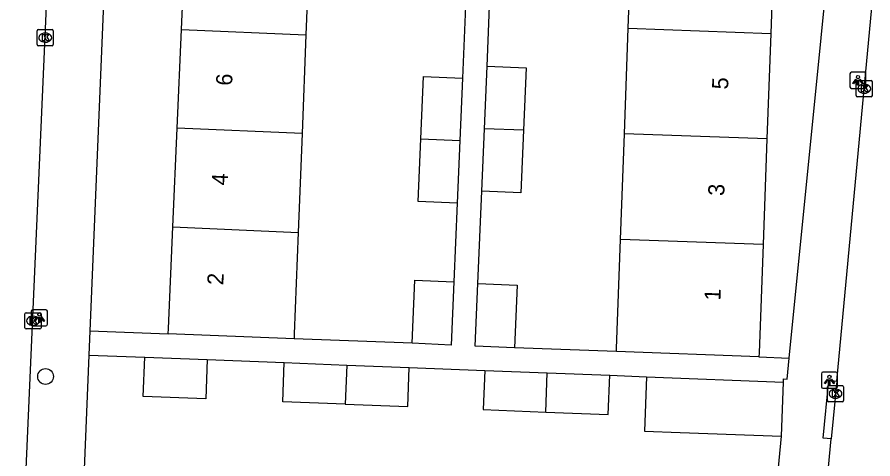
# Model space of a CAD drawing. Extents: x 161355 to 162026, y 386504 to 387459.
# Drawn here: x 161733.6 to 161786.7, y 386670 to 386697.4 of the extents above; entities that cross this region are included whole.
import ezdxf

# ---------------------------------------------------------------- set-up
doc = ezdxf.new("R2010")
doc.units = 0
for name, color, linetype in [('IMGEO_Boom', 7, 'Continuous'), ('IMGEO_Kolk', 7, 'Continuous'), ('IMGEO_Lichtpunt', 7, 'Continuous'), ('IMGEO_Muur', 7, 'Continuous'), ('IMGEO_Pand', 7, 'Continuous'), ('IMGEO_Pand_nummerreeks', 7, 'Continuous'), ('IMGEO_Rijbaan_lokaal_open', 7, 'Continuous'), ('IMGEO_Voetpad_open', 7, 'Continuous')]:
    doc.layers.add(name, color=color, linetype=linetype)

msp = doc.modelspace()

# ---------------------------------------------------------------- linework, layer by layer
at = {"layer": 'IMGEO_Boom'}
msp.add_circle((161735.346, 386675.123), 0.489, dxfattribs=at)
at = {"layer": 'IMGEO_Kolk'}
for p, q in [((161734.826, 386695.717), (161734.826, 386696.569)), ((161734.901, 386696.643), (161735.753, 386696.643)), ((161735.314, 386696.423), (161735.339, 386696.423)), ((161735.827, 386696.569), (161735.827, 386695.717)), ((161735.337, 386695.863), (161735.312, 386695.863)), ((161735.753, 386695.643), (161734.901, 386695.643)), ((161785.645, 386692.551), (161785.645, 386693.403)), ((161785.72, 386693.477), (161786.572, 386693.477)), ((161786.133, 386693.257), (161786.158, 386693.257)), ((161786.646, 386693.403), (161786.646, 386692.551)), ((161786.156, 386692.697), (161786.131, 386692.697)), ((161786.572, 386692.477), (161785.72, 386692.477)), ((161734.065, 386678.151), (161734.065, 386679.003)), ((161734.14, 386679.077), (161734.992, 386679.077)), ((161734.553, 386678.857), (161734.578, 386678.857)), ((161735.066, 386679.003), (161735.066, 386678.151)), ((161734.576, 386678.297), (161734.551, 386678.297)), ((161734.992, 386678.077), (161734.14, 386678.077)), ((161783.86, 386673.63), (161783.86, 386674.482)), ((161783.935, 386674.556), (161784.787, 386674.556)), ((161784.861, 386674.482), (161784.861, 386673.63)), ((161784.348, 386674.336), (161784.373, 386674.336)), ((161784.787, 386673.556), (161783.935, 386673.556)), ((161784.371, 386673.776), (161784.346, 386673.776))]:
    msp.add_line(p, q, dxfattribs=at)
for points in [[(161734.826, 386695.717), (161734.826, 386696.569)], [(161734.901, 386696.643), (161735.753, 386696.643)], [(161735.147, 386696.343), (161735.27, 386696.343), (161735.27, 386696.192), (161735.4, 386696.343), (161735.564, 386696.343), (161735.418, 386696.192), (161735.571, 386695.943), (161735.419, 386695.943), (161735.334, 386696.107), (161735.27, 386696.04), (161735.27, 386695.943), (161735.147, 386695.943), (161735.147, 386696.343)], [(161735.827, 386696.569), (161735.827, 386695.717)], [(161735.753, 386695.643), (161734.901, 386695.643)], [(161785.645, 386692.551), (161785.645, 386693.403)], [(161785.72, 386693.477), (161786.572, 386693.477)], [(161785.966, 386693.177), (161786.089, 386693.177), (161786.089, 386693.026), (161786.219, 386693.177), (161786.383, 386693.177), (161786.237, 386693.026), (161786.39, 386692.777), (161786.238, 386692.777), (161786.153, 386692.941), (161786.089, 386692.874), (161786.089, 386692.777), (161785.966, 386692.777), (161785.966, 386693.177)], [(161786.646, 386693.403), (161786.646, 386692.551)], [(161786.572, 386692.477), (161785.72, 386692.477)], [(161734.065, 386678.151), (161734.065, 386679.003)], [(161734.14, 386679.077), (161734.992, 386679.077)], [(161734.386, 386678.777), (161734.509, 386678.777), (161734.509, 386678.626), (161734.639, 386678.777), (161734.803, 386678.777), (161734.657, 386678.626), (161734.81, 386678.377), (161734.658, 386678.377), (161734.573, 386678.541), (161734.509, 386678.474), (161734.509, 386678.377), (161734.386, 386678.377), (161734.386, 386678.777)], [(161735.066, 386679.003), (161735.066, 386678.151)], [(161734.992, 386678.077), (161734.14, 386678.077)], [(161783.86, 386673.63), (161783.86, 386674.482)], [(161783.935, 386674.556), (161784.787, 386674.556)], [(161784.861, 386674.482), (161784.861, 386673.63)], [(161784.181, 386674.256), (161784.304, 386674.256), (161784.304, 386674.105), (161784.434, 386674.256), (161784.598, 386674.256), (161784.452, 386674.105), (161784.605, 386673.856), (161784.453, 386673.856), (161784.368, 386674.02), (161784.304, 386673.953), (161784.304, 386673.856), (161784.181, 386673.856), (161784.181, 386674.256)], [(161784.787, 386673.556), (161783.935, 386673.556)]]:
    msp.add_lwpolyline(points, dxfattribs=at)
for centre, start, end in [((161734.903, 386696.567), 91.552, 178.448), ((161734.903, 386696.567), 91.552, 178.448), ((161735.751, 386696.567), 1.552, 88.448), ((161735.751, 386696.567), 1.552, 88.448), ((161734.903, 386695.719), 181.552, 268.448), ((161734.903, 386695.719), 181.552, 268.448), ((161735.751, 386695.719), 271.552, 358.448), ((161735.751, 386695.719), 271.552, 358.448), ((161785.722, 386693.401), 91.552, 178.448), ((161785.722, 386693.401), 91.552, 178.448), ((161786.57, 386693.401), 1.552, 88.448), ((161786.57, 386693.401), 1.552, 88.448), ((161785.722, 386692.553), 181.552, 268.448), ((161785.722, 386692.553), 181.552, 268.448), ((161786.57, 386692.553), 271.552, 358.448), ((161786.57, 386692.553), 271.552, 358.448), ((161734.142, 386679.001), 91.552, 178.448), ((161734.142, 386679.001), 91.552, 178.448), ((161734.99, 386679.001), 1.552, 88.448), ((161734.99, 386679.001), 1.552, 88.448), ((161734.142, 386678.153), 181.552, 268.448), ((161734.142, 386678.153), 181.552, 268.448), ((161734.99, 386678.153), 271.552, 358.448), ((161734.99, 386678.153), 271.552, 358.448), ((161783.937, 386674.48), 91.552, 178.448), ((161783.937, 386674.48), 91.552, 178.448), ((161784.785, 386674.48), 1.552, 88.448), ((161784.785, 386674.48), 1.552, 88.448), ((161783.937, 386673.632), 181.552, 268.448), ((161783.937, 386673.632), 181.552, 268.448), ((161784.785, 386673.632), 271.552, 358.448), ((161784.785, 386673.632), 271.552, 358.448)]:
    msp.add_arc(centre, 0.0765, start, end, dxfattribs=at)
for centre, major_axis, ratio, start_param, end_param in [((161735.313, 386696.143), (-0.387, 0.002), 0.722429, 4.712389, 7.853982), ((161735.338, 386696.143), (-0.39, 0.002), 0.717154, 1.570796, 4.712389), ((161786.132, 386692.977), (-0.387, 0.002), 0.722429, 4.712389, 7.853982), ((161786.157, 386692.977), (-0.39, 0.002), 0.717154, 1.570796, 4.712389), ((161734.552, 386678.577), (-0.387, 0.002), 0.722429, 4.712389, 7.853982), ((161734.577, 386678.577), (-0.39, 0.002), 0.717154, 1.570796, 4.712389), ((161784.347, 386674.056), (-0.387, 0.002), 0.722429, 4.712389, 7.853982), ((161784.372, 386674.056), (-0.39, 0.002), 0.717154, 1.570796, 4.712389)]:
    msp.add_ellipse(centre, major_axis=major_axis, ratio=ratio, start_param=start_param, end_param=end_param, dxfattribs=at)
at = {"layer": 'IMGEO_Lichtpunt'}
for p, q in [((161785.256, 386693.899), (161785.256, 386693.092)), ((161785.256, 386693.899), (161785.256, 386693.092)), ((161786.158, 386693.994), (161785.35, 386693.994)), ((161786.158, 386693.994), (161785.35, 386693.994)), ((161786.252, 386693.092), (161786.252, 386693.899)), ((161786.252, 386693.092), (161786.252, 386693.899)), ((161785.35, 386692.998), (161786.158, 386692.998)), ((161785.35, 386692.998), (161786.158, 386692.998)), ((161735.364, 386679.266), (161734.556, 386679.266)), ((161735.364, 386679.266), (161734.556, 386679.266)), ((161734.462, 386679.171), (161734.462, 386678.364)), ((161734.462, 386679.171), (161734.462, 386678.364)), ((161735.458, 386678.364), (161735.458, 386679.171)), ((161735.458, 386678.364), (161735.458, 386679.171)), ((161734.556, 386678.27), (161735.364, 386678.27)), ((161734.556, 386678.27), (161735.364, 386678.27)), ((161783.484, 386675.299), (161783.484, 386674.492)), ((161783.484, 386675.299), (161783.484, 386674.492)), ((161784.386, 386675.394), (161783.578, 386675.394)), ((161784.386, 386675.394), (161783.578, 386675.394)), ((161784.48, 386674.492), (161784.48, 386675.299)), ((161784.48, 386674.492), (161784.48, 386675.299)), ((161783.578, 386674.398), (161784.386, 386674.398)), ((161783.578, 386674.398), (161784.386, 386674.398))]:
    msp.add_line(p, q, dxfattribs=at)
for points in [[(161785.63, 386693.563), (161785.669, 386693.535), (161785.481, 386693.273), (161785.443, 386693.3), (161785.63, 386693.563)], [(161785.732, 386693.515), (161785.779, 386693.515), (161785.779, 386693.193), (161785.732, 386693.193), (161785.732, 386693.515)], [(161785.842, 386693.535), (161785.88, 386693.562), (161786.067, 386693.3), (161786.028, 386693.272), (161785.842, 386693.535)], [(161734.836, 386678.835), (161734.875, 386678.807), (161734.687, 386678.545), (161734.649, 386678.572), (161734.836, 386678.835)], [(161734.938, 386678.787), (161734.985, 386678.787), (161734.985, 386678.465), (161734.938, 386678.465), (161734.938, 386678.787)], [(161735.048, 386678.807), (161735.086, 386678.834), (161735.273, 386678.572), (161735.234, 386678.544), (161735.048, 386678.807)], [(161783.858, 386674.963), (161783.897, 386674.935), (161783.709, 386674.673), (161783.671, 386674.7), (161783.858, 386674.963)], [(161783.96, 386674.915), (161784.007, 386674.915), (161784.007, 386674.593), (161783.96, 386674.593), (161783.96, 386674.915)], [(161784.07, 386674.935), (161784.108, 386674.962), (161784.295, 386674.7), (161784.256, 386674.672), (161784.07, 386674.935)]]:
    msp.add_lwpolyline(points, dxfattribs=at)
for centre in [(161785.755, 386693.697), (161734.961, 386678.969), (161783.983, 386675.097)]:
    msp.add_circle(centre, 0.0994, dxfattribs=at)
for centre, start, end in [((161785.35, 386693.899), 90, 180), ((161785.35, 386693.899), 90, 180), ((161786.158, 386693.899), 0, 90), ((161786.158, 386693.899), 0, 90), ((161785.35, 386693.092), 180, 270), ((161785.35, 386693.092), 180, 270), ((161786.158, 386693.092), 270, 0), ((161786.158, 386693.092), 270, 360), ((161734.556, 386679.171), 90, 180), ((161734.556, 386679.171), 90, 180), ((161735.364, 386679.171), 0, 90), ((161735.364, 386679.171), 0, 90), ((161734.556, 386678.364), 180, 270), ((161734.556, 386678.364), 180, 270), ((161735.364, 386678.364), 270, 0), ((161735.364, 386678.364), 270, 360), ((161783.578, 386675.299), 90, 180), ((161783.578, 386675.299), 90, 180), ((161784.386, 386675.299), 0, 90), ((161784.386, 386675.299), 0, 90), ((161783.578, 386674.492), 180, 270), ((161783.578, 386674.492), 180, 270), ((161784.386, 386674.492), 270, 0), ((161784.386, 386674.492), 270, 360)]:
    msp.add_arc(centre, 0.0946, start, end, dxfattribs=at)
at = {"layer": 'IMGEO_Muur'}
msp.add_lwpolyline([(161780.147, 386662.39), (161781.003, 386671.42)], dxfattribs=at)
at = {"layer": 'IMGEO_Pand'}
for points in [[(161771.496, 386696.73), (161771.734, 386703.279)], [(161743.788, 386696.658), (161744.058, 386702.784)], [(161780.583, 386702.957), (161780.344, 386696.408)], [(161751.741, 386702.445), (161751.501, 386696.318)], [(161743.518, 386690.531), (161743.788, 386696.658)], [(161743.788, 386696.658), (161751.501, 386696.318)], [(161751.501, 386696.318), (161751.261, 386690.19)], [(161771.258, 386690.18), (161771.496, 386696.73)], [(161771.496, 386696.73), (161780.344, 386696.408)], [(161780.344, 386696.408), (161780.105, 386689.858)], [(161762.576, 386690.496), (161762.739, 386694.372)], [(161762.739, 386694.372), (161765.167, 386694.27), (161765.004, 386690.394)], [(161758.625, 386689.857), (161758.787, 386693.734), (161761.215, 386693.632)], [(161761.215, 386693.632), (161761.053, 386689.756)], [(161743.248, 386684.405), (161743.518, 386690.531)], [(161751.261, 386690.19), (161743.518, 386690.531)], [(161762.413, 386686.619), (161762.576, 386690.496)], [(161765.004, 386690.394), (161764.841, 386686.517), (161762.413, 386686.619)], [(161765.004, 386690.394), (161762.576, 386690.496)], [(161751.261, 386690.19), (161751.021, 386684.062)], [(161760.89, 386685.879), (161758.463, 386685.981), (161758.625, 386689.857)], [(161758.625, 386689.857), (161761.053, 386689.756)], [(161771.021, 386683.63), (161771.258, 386690.18)], [(161780.105, 386689.858), (161771.258, 386690.18)], [(161780.105, 386689.858), (161779.867, 386683.308)], [(161761.053, 386689.756), (161760.89, 386685.879)], [(161742.958, 386677.768), (161742.971, 386678.107), (161743.248, 386684.405)], [(161743.248, 386684.405), (161751.021, 386684.062)], [(161751.021, 386684.062), (161750.775, 386677.771), (161750.763, 386677.469)], [(161770.768, 386676.676), (161770.775, 386676.865), (161771.021, 386683.63)], [(161779.867, 386683.308), (161771.021, 386683.63)], [(161779.867, 386683.308), (161779.622, 386676.583), (161779.613, 386676.336)], [(161758.095, 386677.188), (161758.258, 386681.092), (161760.686, 386680.99)], [(161760.686, 386680.99), (161760.522, 386677.076), (161758.095, 386677.188)], [(161764.438, 386676.911), (161762.01, 386677.013), (161762.159, 386680.89)], [(161762.159, 386680.89), (161764.601, 386680.788), (161764.438, 386676.911)], [(161750.763, 386677.469), (161742.958, 386677.768)], [(161779.613, 386676.336), (161770.768, 386676.676)], [(161745.378, 386676.17), (161745.284, 386673.741), (161741.407, 386673.892), (161741.501, 386676.321)], [(161741.501, 386676.321), (161745.378, 386676.17)], [(161753.939, 386673.404), (161750.062, 386673.555), (161750.157, 386675.983)], [(161750.157, 386675.983), (161754.034, 386675.832)], [(161754.034, 386675.832), (161753.939, 386673.404)], [(161753.939, 386673.404), (161757.816, 386673.253), (161757.911, 386675.681)], [(161754.034, 386675.832), (161757.911, 386675.681)], [(161762.599, 386675.499), (161762.504, 386673.07), (161766.381, 386672.919)], [(161762.599, 386675.499), (161766.476, 386675.347)], [(161766.381, 386672.919), (161766.476, 386675.347)], [(161766.381, 386672.919), (161770.258, 386672.768), (161770.353, 386675.196)], [(161766.476, 386675.347), (161770.353, 386675.196)], [(161772.639, 386675.107), (161772.508, 386671.724), (161774.721, 386671.645), (161781.003, 386671.42)], [(161772.639, 386675.107), (161781.124, 386674.777)], [(161781.003, 386671.42), (161781.124, 386674.777)]]:
    msp.add_lwpolyline(points, dxfattribs=at)
at = {"layer": 'IMGEO_Rijbaan_lokaal_open'}
for points in [[(161784.434, 386674.841), (161786.624, 386698.019), (161788.482, 386715.948)], [(161733.581, 386653.996), (161734.07, 386667.509), (161735.471, 386699.54), (161735.824, 386708.256)], [(161784.434, 386674.841), (161784.094, 386671.248)], [(161782.825, 386657.818), (161784.094, 386671.248)]]:
    msp.add_lwpolyline(points, dxfattribs=at)
at = {"layer": 'IMGEO_Voetpad_open'}
for points in [[(161781.487, 386676.264), (161785.465, 386716.028)], [(161742.973, 386715.281), (161740.905, 386715.37), (161740.793, 386715.37), (161740.682, 386715.359), (161740.572, 386715.339), (161740.464, 386715.309), (161740.36, 386715.269), (161740.259, 386715.221), (161740.163, 386715.163), (161740.073, 386715.097), (161739.988, 386715.024), (161739.911, 386714.943), (161739.842, 386714.855), (161739.78, 386714.762), (161739.727, 386714.663), (161739.683, 386714.561), (161739.648, 386714.454), (161739.623, 386714.345), (161739.608, 386714.234), (161739.604, 386714.173), (161738.102, 386677.954)], [(161762.739, 386694.372), (161762.963, 386699.716)], [(161761.402, 386698.102), (161761.215, 386693.632)], [(161762.159, 386680.89), (161762.413, 386686.619)], [(161760.89, 386685.879), (161760.686, 386680.99)], [(161738.102, 386677.954), (161738.04, 386676.455)], [(161738.102, 386677.954), (161742.958, 386677.768)], [(161758.095, 386677.188), (161750.763, 386677.469)], [(161770.768, 386676.676), (161764.438, 386676.911)], [(161738.04, 386676.455), (161737.118, 386654.209)], [(161738.04, 386676.455), (161741.501, 386676.321)], [(161745.378, 386676.17), (161750.157, 386675.983)], [(161779.613, 386676.336), (161781.487, 386676.264)], [(161781.124, 386674.777), (161781.131, 386674.979), (161781.358, 386674.967), (161781.487, 386676.264)], [(161757.911, 386675.681), (161762.599, 386675.499)], [(161770.353, 386675.196), (161772.639, 386675.107)], [(161784.094, 386671.248), (161783.597, 386671.293), (161783.937, 386674.886), (161784.434, 386674.841)], [(161779.2, 386652.395), (161780.147, 386662.39), (161781.003, 386671.42)]]:
    msp.add_lwpolyline(points, dxfattribs=at)

# ---------------------------------------------------------------- texts
at = {"layer": 'IMGEO_Pand_nummerreeks'}
for s, rotation, p in [('6', 87.4784, (161746.917, 386693.148)), ('5', 87.9142, (161777.695, 386692.92)), ('4', 87.4784, (161746.645, 386686.964)), ('3', 87.9142, (161777.454, 386686.312)), ('2', 87.4792, (161746.372, 386680.778)), ('1', 87.9146, (161777.219, 386679.819))]:
    msp.add_text(s, height=1, rotation=rotation, dxfattribs=at).set_placement(p)

doc.saveas('drawing.dxf')
